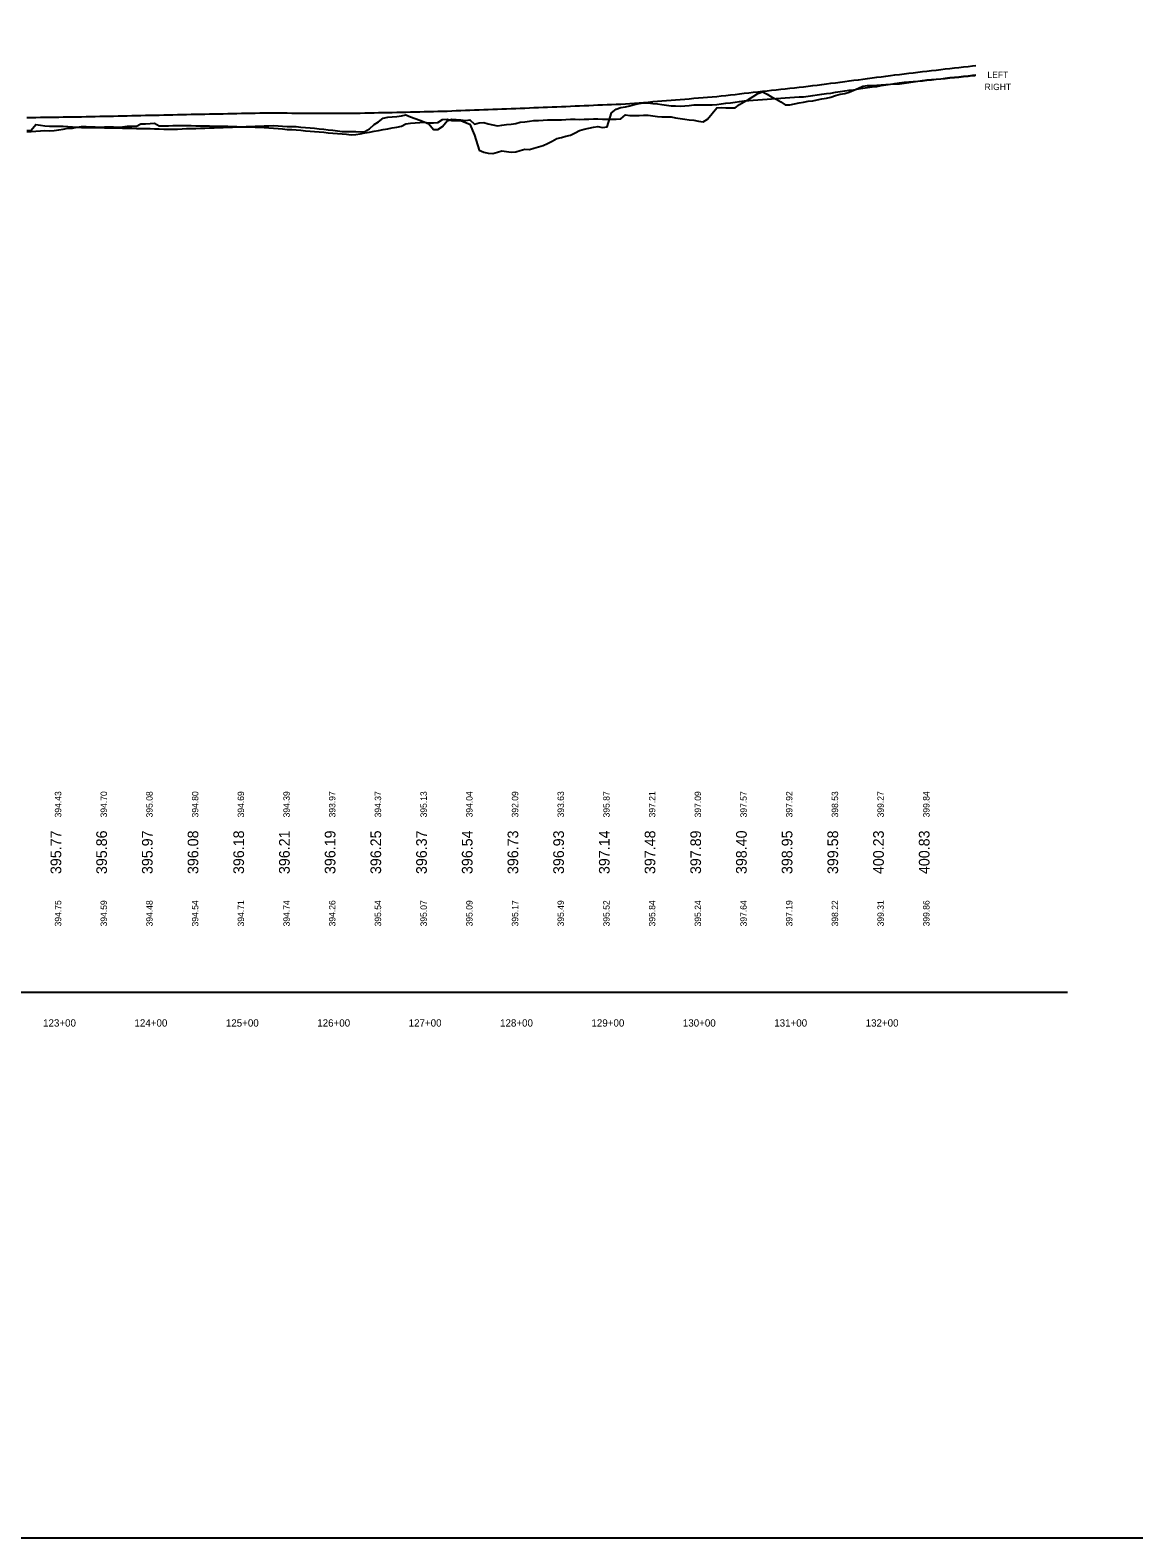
# Model space of a CAD drawing. Extents: x 2084170 to 2089570, y 1072039 to 1077242.
# Drawn here: x 2087155 to 2088362, y 1073942 to 1075592 of the extents above; entities that cross this region are included whole.
import ezdxf

# ---------------------------------------------------------------- set-up
doc = ezdxf.new("R2010")
doc.units = 0
for name, color, linetype in [('RD_DDB_Profile_EX', 7, 'Continuous'), ('RD_DDB_StaTX', 7, 'Continuous'), ('RD_DDB_StripGrade', 7, 'Continuous'), ('RD_GPK_Profile_Cell', 7, 'Continuous'), ('RD_Sketch2', 7, 'Continuous'), ('RD_Sketch3', 7, 'Continuous'), ('RD_Sketch4', 7, 'Continuous')]:
    doc.layers.add(name, color=color, linetype=linetype)

msp = doc.modelspace()

# ---------------------------------------------------------------- linework, layer by layer
at = {"layer": 'RD_DDB_Profile_EX'}
for points in [[(2087701.1, 1075506.9), (2087706.1, 1075507.1), (2087711.1, 1075507.3), (2087716.1, 1075507.5), (2087721.1, 1075507.7), (2087726.1, 1075507.9), (2087731.1, 1075508.1), (2087736.1, 1075508.3), (2087741.1, 1075508.5), (2087746.1, 1075508.7), (2087751.1, 1075508.9), (2087756.1, 1075509.1), (2087761.1, 1075509.4), (2087766.1, 1075509.6), (2087771.1, 1075509.8), (2087776.1, 1075510), (2087781.1, 1075510.2), (2087786.1, 1075510.4), (2087791.1, 1075510.6), (2087796.1, 1075510.8), (2087801.1, 1075511), (2087806.1, 1075511.2), (2087811.1, 1075511.6), (2087816.1, 1075512), (2087821.1, 1075512.4), (2087826.1, 1075512.8), (2087831.1, 1075513.2), (2087836.1, 1075513.7), (2087841.1, 1075514.1), (2087846.1, 1075514.5), (2087851.1, 1075514.9), (2087856.1, 1075515.3), (2087861.1, 1075515.7), (2087866.1, 1075516.1), (2087871.1, 1075516.5), (2087876.1, 1075516.9), (2087881.1, 1075517.3), (2087886.1, 1075517.8), (2087891.1, 1075518.2), (2087896.1, 1075518.6), (2087901.1, 1075519), (2087906.1, 1075519.4), (2087911.1, 1075520), (2087916.1, 1075520.5), (2087921.1, 1075521.1), (2087926.1, 1075521.6), (2087931.1, 1075522.2), (2087936.1, 1075522.8), (2087941.1, 1075523.3), (2087946.1, 1075523.9), (2087951.1, 1075524.4), (2087956.1, 1075525), (2087961.1, 1075525.5), (2087966.1, 1075526.1), (2087971.1, 1075526.6), (2087976.1, 1075527.2), (2087981.1, 1075527.7), (2087986.1, 1075528.3), (2087991.1, 1075528.8), (2087996.1, 1075529.4), (2088001.1, 1075529.9), (2088006.1, 1075530.5), (2088011.1, 1075531.2), (2088016.1, 1075531.8), (2088021.1, 1075532.5), (2088026.1, 1075533.1), (2088031.1, 1075533.8), (2088036.1, 1075534.4), (2088041.1, 1075535.1), (2088046.1, 1075535.7), (2088051.1, 1075536.4), (2088056.1, 1075537), (2088061.1, 1075537.7), (2088066.1, 1075538.3), (2088071.1, 1075539), (2088076.1, 1075539.6), (2088081.1, 1075540.3), (2088086.1, 1075540.9), (2088091.1, 1075541.6), (2088096.1, 1075542.2), (2088101.1, 1075542.9), (2088106.1, 1075543.5), (2088111.1, 1075544.1), (2088116.1, 1075544.7), (2088121.1, 1075545.3), (2088126.1, 1075545.9), (2088131.1, 1075546.5), (2088136.1, 1075547.1), (2088141.1, 1075547.6), (2088146.1, 1075548.2), (2088151.1, 1075548.8), (2088156.1, 1075549.4), (2088161.1, 1075550), (2088166.1, 1075550.6), (2088171.1, 1075551.2), (2088176.1, 1075551.8), (2088181.1, 1075552.3), (2088186.1, 1075552.9), (2088189.4, 1075553.3)], [(2087201.1, 1075497), (2087206.1, 1075497.1), (2087211.1, 1075497.1), (2087216.1, 1075497.3), (2087221.1, 1075497.4), (2087226.1, 1075497.5), (2087231.1, 1075497.6), (2087236.1, 1075497.7), (2087241.1, 1075497.8), (2087246.1, 1075497.9), (2087251.1, 1075498), (2087256.1, 1075498.2), (2087261.1, 1075498.3), (2087266.1, 1075498.4), (2087271.1, 1075498.5), (2087276.1, 1075498.6), (2087281.1, 1075498.7), (2087286.1, 1075498.8), (2087291.1, 1075498.9), (2087296.1, 1075499), (2087301.1, 1075499.2), (2087306.1, 1075499.3), (2087311.1, 1075499.4), (2087316.1, 1075499.5), (2087321.1, 1075499.6), (2087326.1, 1075499.7), (2087331.1, 1075499.8), (2087336.1, 1075499.9), (2087341.1, 1075500), (2087346.1, 1075500.1), (2087351.1, 1075500.2), (2087356.1, 1075500.3), (2087361.1, 1075500.4), (2087366.1, 1075500.5), (2087371.1, 1075500.6), (2087376.1, 1075500.7), (2087381.1, 1075500.8), (2087386.1, 1075500.9), (2087391.1, 1075501), (2087396.1, 1075501.1), (2087401.1, 1075501.2), (2087406.1, 1075501.3), (2087411.1, 1075501.3), (2087416.1, 1075501.3), (2087421.1, 1075501.3), (2087426.1, 1075501.3), (2087431.1, 1075501.3), (2087436.1, 1075501.3), (2087441.1, 1075501.2), (2087446.1, 1075501.2), (2087451.1, 1075501.2), (2087456.1, 1075501.2), (2087461.1, 1075501.2), (2087466.1, 1075501.2), (2087471.1, 1075501.1), (2087476.1, 1075501.1), (2087481.1, 1075501.1), (2087486.1, 1075501.1), (2087491.1, 1075501.1), (2087496.1, 1075501.1), (2087501.1, 1075501.1), (2087506.1, 1075501), (2087511.1, 1075501.1), (2087516.1, 1075501.2), (2087521.1, 1075501.3), (2087526.1, 1075501.4), (2087531.1, 1075501.5), (2087536.1, 1075501.6), (2087541.1, 1075501.7), (2087546.1, 1075501.8), (2087551.1, 1075501.9), (2087556.1, 1075502.1), (2087561.1, 1075502.2), (2087566.1, 1075502.3), (2087571.1, 1075502.4), (2087576.1, 1075502.5), (2087581.1, 1075502.6), (2087586.1, 1075502.7), (2087591.1, 1075502.8), (2087596.1, 1075503), (2087601.1, 1075503.1), (2087606.1, 1075503.2), (2087611.1, 1075503.4), (2087616.1, 1075503.6), (2087621.1, 1075503.8), (2087626.1, 1075504), (2087631.1, 1075504.2), (2087636.1, 1075504.4), (2087641.1, 1075504.6), (2087646.1, 1075504.8), (2087651.1, 1075505), (2087656.1, 1075505.2), (2087661.1, 1075505.3), (2087666.1, 1075505.5), (2087671.1, 1075505.7), (2087676.1, 1075505.9), (2087681.1, 1075506.1), (2087686.1, 1075506.3), (2087691.1, 1075506.5), (2087696.1, 1075506.7), (2087701.1, 1075506.9)], [(2087151.1, 1075496.2), (2087156.1, 1075496.3), (2087161.1, 1075496.4), (2087166.1, 1075496.5), (2087171.1, 1075496.6), (2087176.1, 1075496.6), (2087181.1, 1075496.7), (2087186.1, 1075496.8), (2087191.1, 1075496.9), (2087196.1, 1075496.9), (2087201.1, 1075497)]]:
    msp.add_lwpolyline(points, dxfattribs=at)
at = {"layer": 'RD_GPK_Profile_Cell'}
msp.add_line((2085189.9, 1074539.2), (2088289.9, 1074539.2), dxfattribs=at)
at = {"layer": 'RD_Sketch2'}
msp.add_lwpolyline([(2084170, 1073941.9), (2089570, 1073941.9), (2089570, 1077241.9), (2084170, 1077241.9)], close=True, dxfattribs=at)
at = {"layer": 'RD_Sketch3'}
for points in [[(2087701.1, 1075492.2), (2087706.1, 1075492.9), (2087711.1, 1075493.2), (2087716.1, 1075493.4), (2087721.1, 1075493.6), (2087726.1, 1075493.8), (2087731.1, 1075493.7), (2087736.1, 1075493.9), (2087741.1, 1075494.1), (2087746.1, 1075494.3), (2087751.1, 1075494.5), (2087756.1, 1075494.2), (2087761.1, 1075494.4), (2087766.1, 1075494.6), (2087771.1, 1075494.8), (2087776.1, 1075494.9), (2087781.1, 1075494.6), (2087786.1, 1075494.3), (2087791.1, 1075494.4), (2087796.1, 1075494.6), (2087801.1, 1075494.8), (2087806.1, 1075499.1), (2087811.1, 1075498.6), (2087816.1, 1075498.5), (2087821.1, 1075498.6), (2087826.1, 1075498.7), (2087831.1, 1075498.8), (2087836.1, 1075498.1), (2087841.1, 1075497.4), (2087846.1, 1075497), (2087851.1, 1075497), (2087856.1, 1075497), (2087861.1, 1075496.1), (2087866.1, 1075495.2), (2087871.1, 1075494.3), (2087876.1, 1075493.7), (2087881.1, 1075493.5), (2087886.1, 1075492.4), (2087891.1, 1075491.4), (2087896.1, 1075494.3), (2087901.1, 1075500.6), (2087906.1, 1075506.9), (2087911.1, 1075507.3), (2087916.1, 1075506.9), (2087921.1, 1075506.9), (2087926.1, 1075507), (2087931.1, 1075510.4), (2087936.1, 1075513.5), (2087941.1, 1075516.2), (2087946.1, 1075519.2), (2087951.1, 1075522.5), (2087956.1, 1075524.5), (2087961.1, 1075521.7), (2087966.1, 1075518.9), (2087971.1, 1075516.2), (2087976.1, 1075513.3), (2087981.1, 1075510.1), (2087986.1, 1075510.3), (2087991.1, 1075511.3), (2087996.1, 1075512.2), (2088001.1, 1075513.1), (2088006.1, 1075514), (2088011.1, 1075514.7), (2088016.1, 1075515.7), (2088021.1, 1075516.6), (2088026.1, 1075517.5), (2088031.1, 1075518.6), (2088036.1, 1075520.3), (2088041.1, 1075521.7), (2088046.1, 1075522.4), (2088051.1, 1075524.2), (2088056.1, 1075526.4), (2088061.1, 1075528.5), (2088066.1, 1075530.5), (2088071.1, 1075531.2), (2088076.1, 1075531.5), (2088081.1, 1075531.8), (2088086.1, 1075532), (2088091.1, 1075532.3), (2088096.1, 1075532.8), (2088101.1, 1075533), (2088106.1, 1075533.2), (2088111.1, 1075533.8), (2088116.1, 1075534.6), (2088121.1, 1075535.3), (2088126.1, 1075536.1), (2088131.1, 1075536.9), (2088136.1, 1075537.4), (2088141.1, 1075537.9), (2088146.1, 1075538.4), (2088151.1, 1075538.8), (2088156.1, 1075539.4), (2088161.1, 1075539.9), (2088166.1, 1075540.4), (2088171.1, 1075540.9), (2088176.1, 1075541.4), (2088181.1, 1075542), (2088186.1, 1075542.6), (2088189.4, 1075543)], [(2087151.1, 1075482), (2087156.1, 1075482.5), (2087161.1, 1075488.5), (2087166.1, 1075487.8), (2087171.1, 1075487.3), (2087176.1, 1075486.7), (2087181.1, 1075486.7), (2087186.1, 1075486.7), (2087191.1, 1075486.7), (2087196.1, 1075486.6), (2087201.1, 1075486.1)], [(2087201.1, 1075486.1), (2087206.1, 1075485.7), (2087211.1, 1075485.4), (2087216.1, 1075485.3), (2087221.1, 1075485.3), (2087226.1, 1075485.2), (2087231.1, 1075485.2), (2087236.1, 1075485.1), (2087241.1, 1075485.1), (2087246.1, 1075485), (2087251.1, 1075484.9), (2087256.1, 1075484.8), (2087261.1, 1075484.7), (2087266.1, 1075484.6), (2087271.1, 1075484.4), (2087276.1, 1075484.3), (2087281.1, 1075484.2), (2087286.1, 1075484.1), (2087291.1, 1075484), (2087296.1, 1075483.8), (2087301.1, 1075483.7), (2087306.1, 1075483.6), (2087311.1, 1075483.5), (2087316.1, 1075483.7), (2087321.1, 1075483.9), (2087326.1, 1075484.1), (2087331.1, 1075484.2), (2087336.1, 1075484.4), (2087341.1, 1075484.6), (2087346.1, 1075484.8), (2087351.1, 1075484.9), (2087356.1, 1075485.1), (2087361.1, 1075485.3), (2087366.1, 1075485.4), (2087371.1, 1075485.6), (2087376.1, 1075485.8), (2087381.1, 1075486), (2087386.1, 1075486.2), (2087391.1, 1075486.3), (2087396.1, 1075486.5), (2087401.1, 1075486.7), (2087406.1, 1075486.9), (2087411.1, 1075487.1), (2087416.1, 1075487.3), (2087421.1, 1075487.5), (2087426.1, 1075487.3), (2087431.1, 1075486.8), (2087436.1, 1075486.6), (2087441.1, 1075486.6), (2087446.1, 1075486.3), (2087451.1, 1075485.8), (2087456.1, 1075485.3), (2087461.1, 1075484.9), (2087466.1, 1075484.6), (2087471.1, 1075484), (2087476.1, 1075483.4), (2087481.1, 1075482.8), (2087486.1, 1075482.3), (2087491.1, 1075481.6), (2087496.1, 1075481.1), (2087501.1, 1075481.1), (2087506.1, 1075481.1), (2087511.1, 1075480.9), (2087516.1, 1075480.7), (2087521.1, 1075480.9), (2087526.1, 1075483.9), (2087531.1, 1075488.6), (2087536.1, 1075491.7), (2087541.1, 1075495.5), (2087546.1, 1075496.5), (2087551.1, 1075496.9), (2087556.1, 1075497.4), (2087561.1, 1075498.2), (2087566.1, 1075499.3), (2087571.1, 1075497), (2087576.1, 1075495.2), (2087581.1, 1075493.4), (2087586.1, 1075491.7), (2087591.1, 1075489.3), (2087596.1, 1075483), (2087601.1, 1075483.3), (2087606.1, 1075486.3), (2087611.1, 1075492.6), (2087616.1, 1075494.4), (2087621.1, 1075494.2), (2087626.1, 1075493.6), (2087631.1, 1075493), (2087636.1, 1075493.6), (2087641.1, 1075489), (2087646.1, 1075490.4), (2087651.1, 1075490.7), (2087656.1, 1075489.5), (2087661.1, 1075488.3), (2087666.1, 1075487.2), (2087671.1, 1075487.9), (2087676.1, 1075488.5), (2087681.1, 1075489.1), (2087686.1, 1075489.8), (2087691.1, 1075491.2), (2087696.1, 1075491.7), (2087701.1, 1075492.2)]]:
    msp.add_lwpolyline(points, dxfattribs=at)
at = {"layer": 'RD_Sketch4'}
for points in [[(2087701.1, 1075461.4), (2087706.1, 1075462.7), (2087711.1, 1075464.1), (2087716.1, 1075465.5), (2087721.1, 1075467.7), (2087726.1, 1075470.5), (2087731.1, 1075473.2), (2087736.1, 1075474.5), (2087741.1, 1075475.8), (2087746.1, 1075477), (2087751.1, 1075479.5), (2087756.1, 1075482.1), (2087761.1, 1075483.5), (2087766.1, 1075484.7), (2087771.1, 1075485.8), (2087776.1, 1075486.5), (2087781.1, 1075485.2), (2087786.1, 1075486.2), (2087791.1, 1075501.4), (2087796.1, 1075505.3), (2087801.1, 1075507.2), (2087806.1, 1075508.1), (2087811.1, 1075509.2), (2087816.1, 1075510.6), (2087821.1, 1075511.7), (2087826.1, 1075512.2), (2087831.1, 1075512.3), (2087836.1, 1075511.7), (2087841.1, 1075511.2), (2087846.1, 1075510.5), (2087851.1, 1075509.9), (2087856.1, 1075509.2), (2087861.1, 1075508.9), (2087866.1, 1075508.7), (2087871.1, 1075509.1), (2087876.1, 1075509.6), (2087881.1, 1075510), (2087886.1, 1075510.1), (2087891.1, 1075510.1), (2087896.1, 1075510.2), (2087901.1, 1075510.2), (2087906.1, 1075510.5), (2087911.1, 1075511.2), (2087916.1, 1075511.9), (2087921.1, 1075512.5), (2087926.1, 1075513.2), (2087931.1, 1075513.9), (2087936.1, 1075514.5), (2087941.1, 1075515), (2087946.1, 1075515.4), (2087951.1, 1075515.7), (2087956.1, 1075516.1), (2087961.1, 1075516.4), (2087966.1, 1075516.8), (2087971.1, 1075517.2), (2087976.1, 1075517.5), (2087981.1, 1075517.8), (2087986.1, 1075518.1), (2087991.1, 1075518.4), (2087996.1, 1075518.8), (2088001.1, 1075519.1), (2088006.1, 1075519.6), (2088011.1, 1075520.4), (2088016.1, 1075521.1), (2088021.1, 1075521.9), (2088026.1, 1075522.5), (2088031.1, 1075523.1), (2088036.1, 1075523.9), (2088041.1, 1075524.6), (2088046.1, 1075525.4), (2088051.1, 1075526.1), (2088056.1, 1075526.7), (2088061.1, 1075527.5), (2088066.1, 1075528.3), (2088071.1, 1075529), (2088076.1, 1075529.8), (2088081.1, 1075530.4), (2088086.1, 1075531.2), (2088091.1, 1075532), (2088096.1, 1075532.8), (2088101.1, 1075533.6), (2088106.1, 1075534.3), (2088111.1, 1075534.8), (2088116.1, 1075535.3), (2088121.1, 1075535.7), (2088126.1, 1075536.2), (2088131.1, 1075536.6), (2088136.1, 1075537.2), (2088141.1, 1075537.7), (2088146.1, 1075538.1), (2088151.1, 1075538.6), (2088156.1, 1075539.1), (2088161.1, 1075539.7), (2088166.1, 1075540.1), (2088171.1, 1075540.6), (2088176.1, 1075541.1), (2088181.1, 1075541.5), (2088186.1, 1075542.1), (2088189, 1075542.3)], [(2087201.1, 1075484.7), (2087206.1, 1075485.8), (2087211.1, 1075486.6), (2087216.1, 1075486.4), (2087221.1, 1075486.2), (2087226.1, 1075486), (2087231.1, 1075485.9), (2087236.1, 1075486.2), (2087241.1, 1075486.1), (2087246.1, 1075486), (2087251.1, 1075485.9), (2087256.1, 1075486.2), (2087261.1, 1075486.7), (2087266.1, 1075486.9), (2087271.1, 1075486.9), (2087276.1, 1075489.4), (2087281.1, 1075489.4), (2087286.1, 1075489.7), (2087291.1, 1075490.1), (2087296.1, 1075487.3), (2087301.1, 1075487.3), (2087306.1, 1075487.3), (2087311.1, 1075487.6), (2087316.1, 1075487.5), (2087321.1, 1075487.5), (2087326.1, 1075487.5), (2087331.1, 1075487.4), (2087336.1, 1075487.2), (2087341.1, 1075487.2), (2087346.1, 1075487.2), (2087351.1, 1075487.1), (2087356.1, 1075487), (2087361.1, 1075486.7), (2087366.1, 1075486.7), (2087371.1, 1075486.7), (2087376.1, 1075486.6), (2087381.1, 1075486.4), (2087386.1, 1075486.1), (2087391.1, 1075486.1), (2087396.1, 1075486), (2087401.1, 1075485.9), (2087406.1, 1075485.6), (2087411.1, 1075485.3), (2087416.1, 1075485), (2087421.1, 1075484.8), (2087426.1, 1075484.3), (2087431.1, 1075483.8), (2087436.1, 1075483.3), (2087441.1, 1075483), (2087446.1, 1075482.7), (2087451.1, 1075482.3), (2087456.1, 1075481.7), (2087461.1, 1075481.3), (2087466.1, 1075480.9), (2087471.1, 1075480.6), (2087476.1, 1075480.1), (2087481.1, 1075479.6), (2087486.1, 1075479.1), (2087491.1, 1075478.8), (2087496.1, 1075478.5), (2087501.1, 1075478), (2087506.1, 1075477.4), (2087511.1, 1075477.7), (2087516.1, 1075478.6), (2087521.1, 1075479.5), (2087526.1, 1075480.4), (2087531.1, 1075481.3), (2087536.1, 1075482.2), (2087541.1, 1075483.1), (2087546.1, 1075484), (2087551.1, 1075484.9), (2087556.1, 1075485.8), (2087561.1, 1075486.7), (2087566.1, 1075489.4), (2087571.1, 1075490), (2087576.1, 1075490.5), (2087581.1, 1075491), (2087586.1, 1075491.1), (2087591.1, 1075490.3), (2087596.1, 1075490.4), (2087601.1, 1075491), (2087606.1, 1075494.1), (2087611.1, 1075494.6), (2087616.1, 1075493.2), (2087621.1, 1075493.1), (2087626.1, 1075492.9), (2087631.1, 1075490.9), (2087636.1, 1075488.9), (2087641.1, 1075476.8), (2087646.1, 1075460.4), (2087651.1, 1075458.2), (2087656.1, 1075457.1), (2087661.1, 1075457), (2087666.1, 1075458.5), (2087671.1, 1075459.9), (2087676.1, 1075459.2), (2087681.1, 1075458.4), (2087686.1, 1075458.9), (2087691.1, 1075460.3), (2087696.1, 1075461.7), (2087701.1, 1075461.4)], [(2087151.1, 1075481), (2087156.1, 1075481.1), (2087161.1, 1075481.3), (2087166.1, 1075481.8), (2087171.1, 1075482), (2087176.1, 1075481.8), (2087181.1, 1075481.9), (2087186.1, 1075482.8), (2087191.1, 1075483.6), (2087196.1, 1075484.5), (2087201.1, 1075484.7)]]:
    msp.add_lwpolyline(points, dxfattribs=at)

# ---------------------------------------------------------------- texts
at = {"layer": 'RD_DDB_StaTX'}
for s, p in [('123+00', (2087169, 1074501.4)), ('124+00', (2087269, 1074501.4)), ('125+00', (2087369, 1074501.4)), ('126+00', (2087469, 1074501.4)), ('127+00', (2087569, 1074501.4)), ('128+00', (2087669, 1074501.4)), ('129+00', (2087769, 1074501.4)), ('130+00', (2087869, 1074501.4)), ('131+00', (2087969, 1074501.4)), ('132+00', (2088069, 1074501.4))]:
    msp.add_text(s, height=8, dxfattribs=at).set_placement(p)
at = {"layer": 'RD_DDB_StripGrade'}
for s, p in [('395.77', (2087188.9, 1074668.3)), ('395.86', (2087238.9, 1074668.3)), ('395.97', (2087288.9, 1074668.3)), ('396.08', (2087338.9, 1074668.3)), ('396.18', (2087388.9, 1074668.3)), ('396.21', (2087438.9, 1074668.3)), ('396.19', (2087488.9, 1074668.3)), ('396.25', (2087538.9, 1074668.3)), ('396.37', (2087588.9, 1074668.3)), ('396.54', (2087638.9, 1074668.3)), ('396.73', (2087688.9, 1074668.3)), ('396.93', (2087738.9, 1074668.3)), ('397.14', (2087788.9, 1074668.3)), ('397.48', (2087838.9, 1074668.3)), ('397.89', (2087888.9, 1074668.3)), ('398.40', (2087938.9, 1074668.3)), ('398.95', (2087988.9, 1074668.3)), ('399.58', (2088038.9, 1074668.3)), ('400.23', (2088088.9, 1074668.3)), ('400.83', (2088138.9, 1074668.3))]:
    msp.add_text(s, height=11.67, rotation=90, dxfattribs=at).set_placement(p)
at = {"layer": 'RD_Sketch3'}
msp.add_text('LEFT', height=7, dxfattribs=at).set_placement((2088202.2, 1075539.5))
for s, p in [('394.75', (2087188.9, 1074611)), ('394.59', (2087238.9, 1074611)), ('394.48', (2087288.9, 1074611)), ('394.54', (2087338.9, 1074611)), ('394.71', (2087388.9, 1074611)), ('394.74', (2087438.9, 1074611)), ('394.26', (2087488.9, 1074611)), ('395.54', (2087538.9, 1074611)), ('395.07', (2087588.9, 1074611)), ('395.09', (2087638.9, 1074611)), ('395.17', (2087688.9, 1074611)), ('395.49', (2087738.9, 1074611)), ('395.52', (2087788.9, 1074611)), ('395.84', (2087838.9, 1074611)), ('395.24', (2087888.9, 1074611)), ('397.64', (2087938.9, 1074611)), ('397.19', (2087988.9, 1074611)), ('398.22', (2088038.9, 1074611)), ('399.31', (2088088.9, 1074611)), ('399.86', (2088138.9, 1074611))]:
    msp.add_text(s, height=7, rotation=90, dxfattribs=at).set_placement(p)
at = {"layer": 'RD_Sketch4'}
msp.add_text('RIGHT', height=7, dxfattribs=at).set_placement((2088199.1, 1075526.3))
for s, p in [('394.43', (2087188.9, 1074730.3)), ('394.70', (2087238.9, 1074730.3)), ('395.08', (2087288.9, 1074730.3)), ('394.80', (2087338.9, 1074730.3)), ('394.69', (2087388.9, 1074730.3)), ('394.39', (2087438.9, 1074730.3)), ('393.97', (2087488.9, 1074730.3)), ('394.37', (2087538.9, 1074730.3)), ('395.13', (2087588.9, 1074730.3)), ('394.04', (2087638.9, 1074730.3)), ('392.09', (2087688.9, 1074730.3)), ('393.63', (2087738.9, 1074730.3)), ('395.87', (2087788.9, 1074730.3)), ('397.21', (2087838.9, 1074730.3)), ('397.09', (2087888.9, 1074730.3)), ('397.57', (2087938.9, 1074730.3)), ('397.92', (2087988.9, 1074730.3)), ('398.53', (2088038.9, 1074730.3)), ('399.27', (2088088.9, 1074730.3)), ('399.84', (2088138.9, 1074730.3))]:
    msp.add_text(s, height=7, rotation=90, dxfattribs=at).set_placement(p)

doc.saveas('drawing.dxf')
